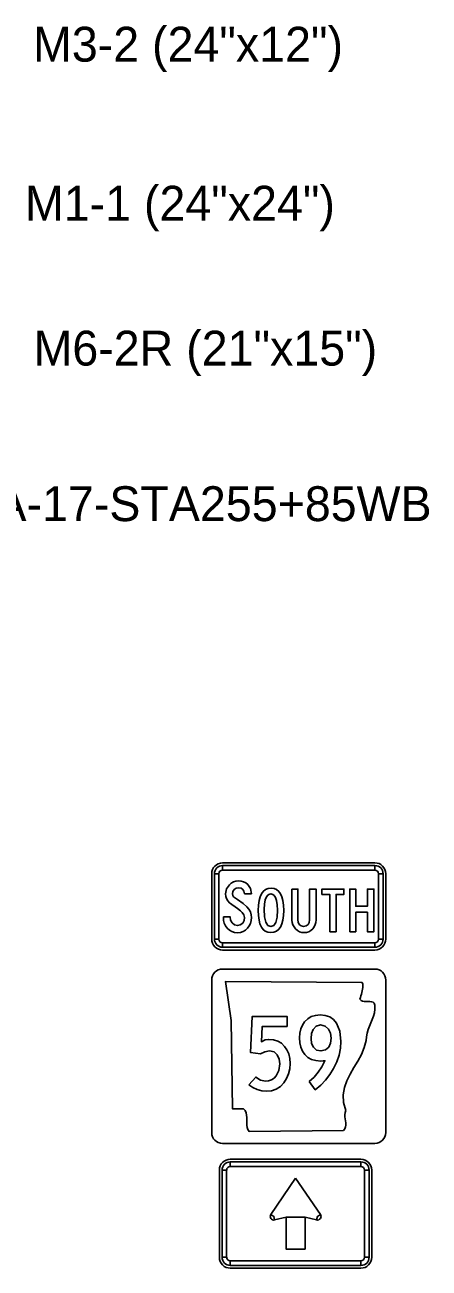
# Model space of a CAD drawing. Extents: x 620856.8 to 620948.6, y 415598.8 to 415658.2.
# Drawn here: x 620899.13 to 620903.77, y 415641.2 to 415655.46 of the extents above; entities that cross this region are included whole.
import ezdxf

# ---------------------------------------------------------------- set-up
doc = ezdxf.new("R2010")
doc.units = 0
doc.layers.add('SIGNS', color=7, linetype='Continuous')

msp = doc.modelspace()

# ---------------------------------------------------------------- linework, layer by layer
at = {"layer": 'SIGNS'}
for p, q in [((620903.15, 415645.852), (620901.4, 415645.852)), ((620901.4, 415645.769), (620901.4, 415645.821)), ((620903.15, 415645.821), (620903.15, 415645.769)), ((620901.275, 415645.727), (620901.275, 415644.977)), ((620901.306, 415645.727), (620901.358, 415645.727)), ((620903.192, 415645.727), (620903.244, 415645.727)), ((620903.275, 415644.977), (620903.275, 415645.727)), ((620901.358, 415644.977), (620901.306, 415644.977)), ((620901.4, 415644.884), (620901.4, 415644.936)), ((620903.15, 415644.936), (620903.15, 415644.884)), ((620903.244, 415644.977), (620903.192, 415644.977)), ((620901.4, 415644.852), (620903.15, 415644.852)), ((620903.15, 415644.633), (620901.4, 415644.633)), ((620901.275, 415644.508), (620901.275, 415642.758)), ((620903.275, 415642.758), (620903.275, 415644.508)), ((620901.275, 415642.758), (620901.275, 415642.758)), ((620901.4, 415642.633), (620903.15, 415642.633)), ((620902.989, 415642.453), (620901.489, 415642.453)), ((620901.489, 415642.37), (620901.489, 415642.422)), ((620902.989, 415642.422), (620902.989, 415642.37)), ((620901.364, 415642.328), (620901.364, 415641.328)), ((620901.395, 415642.328), (620901.447, 415642.328)), ((620903.031, 415642.328), (620903.083, 415642.328)), ((620903.114, 415641.328), (620903.114, 415642.328)), ((620901.989, 415641.797), (620901.954, 415641.819)), ((620901.998, 415641.757), (620901.989, 415641.797)), ((620902.489, 415641.797), (620902.48, 415641.757)), ((620902.524, 415641.819), (620902.489, 415641.797)), ((620901.447, 415641.328), (620901.395, 415641.328)), ((620901.489, 415641.235), (620901.489, 415641.287)), ((620901.489, 415641.203), (620902.989, 415641.203)), ((620902.989, 415641.287), (620902.989, 415641.235)), ((620903.083, 415641.328), (620903.031, 415641.328))]:
    msp.add_line(p, q, dxfattribs=at)
for points in [[(620903.15, 415645.821), (620901.4, 415645.821), (620901.4, 415645.769), (620903.15, 415645.769), (620903.15, 415645.821), (620903.15, 415645.821)], [(620901.306, 415645.727), (620901.306, 415644.977), (620901.358, 415644.977), (620901.358, 415645.727), (620901.306, 415645.727), (620901.306, 415645.727)], [(620901.409, 415645.232), (620901.409, 415645.227), (620901.411, 415645.192), (620901.419, 415645.16), (620901.434, 415645.131), (620901.453, 415645.104), (620901.478, 415645.08), (620901.506, 415645.063), (620901.537, 415645.053), (620901.571, 415645.049), (620901.605, 415645.053), (620901.636, 415645.063), (620901.663, 415645.079), (620901.688, 415645.102), (620901.707, 415645.128), (620901.721, 415645.158), (620901.729, 415645.189), (620901.732, 415645.224), (620901.728, 415645.257), (620901.719, 415645.289), (620901.703, 415645.319), (620901.68, 415645.347), (620901.637, 415645.384), (620901.571, 415645.43), (620901.527, 415645.462), (620901.517, 415645.479), (620901.514, 415645.498), (620901.519, 415645.524), (620901.535, 415645.545), (620901.557, 415645.56), (620901.584, 415645.565), (620901.612, 415645.56), (620901.633, 415645.546), (620901.644, 415645.527), (620901.652, 415645.498), (620901.732, 415645.498), (620901.719, 415645.557), (620901.689, 415645.603), (620901.666, 415645.621), (620901.641, 415645.634), (620901.613, 415645.641), (620901.581, 415645.644), (620901.552, 415645.641), (620901.525, 415645.633), (620901.5, 415645.619), (620901.478, 415645.6), (620901.445, 415645.552), (620901.435, 415645.496), (620901.437, 415645.467), (620901.446, 415645.441), (620901.459, 415645.417), (620901.479, 415645.394), (620901.571, 415645.328), (620901.606, 415645.302), (620901.627, 415645.282), (620901.646, 415645.254), (620901.653, 415645.223), (620901.647, 415645.189), (620901.631, 415645.161), (620901.604, 415645.14), (620901.571, 415645.133), (620901.536, 415645.14), (620901.509, 415645.164), (620901.493, 415645.195), (620901.488, 415645.232)], [(620903.244, 415644.977), (620903.244, 415645.727), (620903.192, 415645.727), (620903.192, 415644.977), (620903.244, 415644.977), (620903.244, 415644.977)], [(620902.197, 415645.551), (620902.197, 415645.196), (620902.2, 415645.167), (620902.208, 415645.14), (620902.221, 415645.116), (620902.239, 415645.094), (620902.259, 415645.075), (620902.283, 415645.062), (620902.309, 415645.054), (620902.338, 415645.051), (620902.366, 415645.054), (620902.391, 415645.062), (620902.415, 415645.076), (620902.436, 415645.096), (620902.453, 415645.118), (620902.465, 415645.143), (620902.472, 415645.169), (620902.474, 415645.197), (620902.474, 415645.551), (620902.399, 415645.551), (620902.399, 415645.2), (620902.395, 415645.169), (620902.382, 415645.145), (620902.36, 415645.128), (620902.331, 415645.122), (620902.303, 415645.128), (620902.281, 415645.146), (620902.269, 415645.171), (620902.265, 415645.2), (620902.265, 415645.551)], [(620902.632, 415645.061), (620902.703, 415645.061), (620902.703, 415645.489), (620902.794, 415645.489), (620902.794, 415645.551), (620902.542, 415645.551), (620902.542, 415645.489), (620902.632, 415645.489)], [(620902.861, 415645.061), (620902.929, 415645.061), (620902.929, 415645.286), (620903.063, 415645.286), (620903.063, 415645.061), (620903.138, 415645.061), (620903.138, 415645.551), (620903.063, 415645.551), (620903.063, 415645.354), (620902.929, 415645.354), (620902.929, 415645.551), (620902.861, 415645.551)], [(620901.4, 415644.884), (620903.15, 415644.884), (620903.15, 415644.936), (620901.4, 415644.936), (620901.4, 415644.884), (620901.4, 415644.884)], [(620903.005, 415644.479), (620903.01, 415644.46), (620903.011, 415644.44), (620903.011, 415644.421), (620903.008, 415644.402), (620903.004, 415644.383), (620903, 415644.364), (620902.994, 415644.345), (620902.988, 415644.327), (620902.983, 415644.309), (620902.978, 415644.29), (620902.992, 415644.274), (620903.009, 415644.265), (620903.029, 415644.261), (620903.051, 415644.26), (620903.072, 415644.261), (620903.093, 415644.262), (620903.112, 415644.259), (620903.128, 415644.253), (620903.141, 415644.241), (620903.149, 415644.221), (620903.15, 415644.175), (620903.144, 415644.133), (620903.134, 415644.092), (620903.119, 415644.054), (620903.104, 415644.016), (620903.088, 415643.978), (620903.073, 415643.939), (620903.061, 415643.9), (620903.052, 415643.858), (620903.05, 415643.814), (620903.028, 415643.732), (620902.994, 415643.654), (620902.954, 415643.578), (620902.909, 415643.503), (620902.866, 415643.429), (620902.829, 415643.353), (620902.801, 415643.274), (620902.786, 415643.191), (620902.789, 415643.104), (620902.815, 415643.01), (620902.808, 415642.987), (620902.805, 415642.963), (620902.806, 415642.94), (620902.809, 415642.915), (620902.812, 415642.891), (620902.815, 415642.868), (620902.815, 415642.845), (620902.812, 415642.823), (620902.804, 415642.802), (620902.788, 415642.782), (620901.704, 415642.772), (620901.69, 415642.792), (620901.681, 415642.816), (620901.678, 415642.842), (620901.677, 415642.871), (620901.678, 415642.9), (620901.678, 415642.93), (620901.676, 415642.959), (620901.671, 415642.985), (620901.66, 415643.01), (620901.641, 415643.03), (620901.515, 415643.03), (620901.497, 415644.042), (620901.433, 415644.489), (620903.005, 415644.479), (620903.005, 415644.479)], [(620901.7, 415643.307), (620901.748, 415643.274), (620901.798, 415643.251), (620901.85, 415643.237), (620901.905, 415643.233), (620901.964, 415643.238), (620902.017, 415643.257), (620902.064, 415643.287), (620902.105, 415643.33), (620902.136, 415643.378), (620902.157, 415643.43), (620902.171, 415643.488), (620902.175, 415643.551), (620902.171, 415643.608), (620902.16, 415643.66), (620902.14, 415643.706), (620902.113, 415643.747), (620902.077, 415643.782), (620902.034, 415643.806), (620901.985, 415643.821), (620901.931, 415643.827), (620901.89, 415643.82), (620901.846, 415643.8), (620901.855, 415643.975), (620902.142, 415643.975), (620902.142, 415644.091), (620901.741, 415644.091), (620901.721, 415643.675), (620901.837, 415643.66), (620901.886, 415643.686), (620901.939, 415643.695), (620901.991, 415643.683), (620902.029, 415643.648), (620902.049, 415643.602), (620902.056, 415643.545), (620902.046, 415643.47), (620902.016, 415643.409), (620901.991, 415643.382), (620901.962, 415643.363), (620901.929, 415643.352), (620901.892, 415643.348), (620901.835, 415643.36), (620901.781, 415643.395)], [(620902.989, 415642.422), (620901.489, 415642.422), (620901.489, 415642.37), (620902.989, 415642.37), (620902.989, 415642.422), (620902.989, 415642.422)], [(620901.395, 415642.328), (620901.395, 415641.328), (620901.447, 415641.328), (620901.447, 415642.328), (620901.395, 415642.328), (620901.395, 415642.328)], [(620902.239, 415642.235), (620901.954, 415641.819), (620901.989, 415641.797), (620901.998, 415641.757), (620902.13, 415641.787), (620902.348, 415641.787), (620902.48, 415641.757), (620902.489, 415641.797), (620902.524, 415641.819), (620902.239, 415642.235), (620902.239, 415642.235)], [(620903.083, 415641.328), (620903.083, 415642.328), (620903.031, 415642.328), (620903.031, 415641.328), (620903.083, 415641.328), (620903.083, 415641.328)], [(620902.348, 415641.422), (620902.13, 415641.422), (620902.13, 415641.787), (620902.348, 415641.787), (620902.348, 415641.422), (620902.348, 415641.422)], [(620901.489, 415641.235), (620902.989, 415641.235), (620902.989, 415641.287), (620901.489, 415641.287), (620901.489, 415641.235), (620901.489, 415641.235)]]:
    msp.add_lwpolyline(points, close=True, dxfattribs=at)
for points in [[(620902.102, 415645.306), (620902.1, 415645.366), (620902.093, 415645.418), (620902.082, 415645.461), (620902.066, 415645.497), (620902.045, 415645.525), (620902.02, 415645.545), (620901.991, 415645.556), (620901.957, 415645.561), (620901.923, 415645.556), (620901.893, 415645.545), (620901.868, 415645.525), (620901.847, 415645.497), (620901.831, 415645.461), (620901.819, 415645.418), (620901.813, 415645.366), (620901.81, 415645.306), (620901.812, 415645.246), (620901.819, 415645.195), (620901.83, 415645.151), (620901.846, 415645.115), (620901.866, 415645.087), (620901.891, 415645.067), (620901.92, 415645.055), (620901.954, 415645.051), (620901.989, 415645.055), (620902.019, 415645.067), (620902.044, 415645.087), (620902.065, 415645.115), (620902.081, 415645.151), (620902.093, 415645.195), (620902.1, 415645.246), (620902.102, 415645.306)], [(620902.031, 415645.309), (620902.027, 415645.227), (620902.012, 415645.169), (620901.988, 415645.134), (620901.955, 415645.122), (620901.921, 415645.135), (620901.897, 415645.172), (620901.882, 415645.234), (620901.878, 415645.321), (620901.881, 415645.379), (620901.89, 415645.427), (620901.901, 415645.456), (620901.916, 415645.478), (620901.933, 415645.49), (620901.955, 415645.495), (620901.976, 415645.49), (620901.994, 415645.476), (620902.008, 415645.453), (620902.02, 415645.421), (620902.028, 415645.37), (620902.031, 415645.309)], [(620901.4, 415644.633), (620901.4, 415644.633)], [(620903.15, 415644.633), (620903.15, 415644.633)], [(620901.275, 415644.508), (620901.275, 415644.508)], [(620902.396, 415643.344), (620902.464, 415643.249), (620902.527, 415643.302), (620902.583, 415643.36), (620902.632, 415643.424), (620902.676, 415643.494), (620902.712, 415643.57), (620902.738, 415643.647), (620902.753, 415643.725), (620902.759, 415643.804), (620902.746, 415643.923), (620902.709, 415644.014), (620902.674, 415644.055), (620902.631, 415644.084), (620902.58, 415644.101), (620902.521, 415644.107), (620902.467, 415644.102), (620902.419, 415644.088), (620902.378, 415644.064), (620902.343, 415644.03), (620902.317, 415643.991), (620902.298, 415643.947), (620902.287, 415643.898), (620902.284, 415643.844), (620902.287, 415643.786), (620902.299, 415643.736), (620902.318, 415643.691), (620902.345, 415643.653), (620902.381, 415643.62), (620902.423, 415643.597), (620902.473, 415643.583), (620902.53, 415643.578), (620902.554, 415643.58), (620902.577, 415643.582), (620902.575, 415643.582), (620902.541, 415643.512), (620902.5, 415643.45), (620902.452, 415643.394), (620902.396, 415643.344)], [(620902.647, 415643.841), (620902.64, 415643.784), (620902.619, 415643.739), (620902.582, 415643.706), (620902.53, 415643.695), (620902.48, 415643.705), (620902.443, 415643.737), (620902.422, 415643.781), (620902.416, 415643.836), (620902.421, 415643.894), (620902.439, 415643.941), (620902.475, 415643.979), (620902.526, 415643.992), (620902.577, 415643.98), (620902.617, 415643.944), (620902.639, 415643.897), (620902.647, 415643.841)], [(620901.4, 415642.633), (620901.4, 415642.633)], [(620903.15, 415642.633), (620903.15, 415642.633)]]:
    msp.add_lwpolyline(points, dxfattribs=at)
for centre, radius, start, end in [((620901.4, 415645.727), 0.125, 90.0002, 179.9998), ((620901.4, 415645.727), 0.0937, 90.0002, 179.9998), ((620901.4, 415645.727), 0.0417, 90.0002, 179.9998), ((620903.15, 415645.727), 0.125, 360, 90.0002), ((620903.15, 415645.727), 0.0937, 360, 90.0002), ((620903.15, 415645.727), 0.0417, 360, 90.0002), ((620901.4, 415644.977), 0.125, 179.9998, 270.0001), ((620901.4, 415644.977), 0.0937, 179.9998, 270.0001), ((620901.4, 415644.977), 0.0417, 179.9998, 270.0001), ((620903.15, 415644.977), 0.125, 270.0001, 0.0003), ((620903.15, 415644.977), 0.0937, 270.0001, 0.0003), ((620903.15, 415644.977), 0.0417, 270.0001, 0.0003), ((620901.4, 415644.508), 0.125, 90.0002, 179.9998), ((620903.15, 415644.508), 0.125, 360, 90), ((620901.4, 415642.758), 0.125, 180, 270), ((620903.15, 415642.758), 0.125, 270.0001, 0.0003), ((620901.489, 415642.328), 0.125, 90.0002, 179.9998), ((620901.489, 415642.328), 0.0937, 90.0002, 179.9998), ((620901.489, 415642.328), 0.0417, 90.0002, 179.9998), ((620902.989, 415642.328), 0.125, 360, 90.0002), ((620902.989, 415642.328), 0.0937, 360, 90.0002), ((620902.989, 415642.328), 0.0417, 360, 90.0002), ((620901.989, 415641.797), 0.0417, 147.7246, 282.9506), ((620902.489, 415641.797), 0.0417, 257.0495, 32.2756), ((620901.489, 415641.328), 0.125, 179.9998, 270.0001), ((620901.489, 415641.328), 0.0937, 179.9998, 270.0001), ((620901.489, 415641.328), 0.0417, 179.9998, 270.0001), ((620902.989, 415641.328), 0.0937, 270.0001, 0.0003), ((620902.989, 415641.328), 0.0417, 270.0001, 0.0003), ((620902.989, 415641.328), 0.125, 270.0001, 0.0003)]:
    msp.add_arc(centre, radius, start, end, dxfattribs=at)

# ---------------------------------------------------------------- texts
for s, p in [('M3-2 (24"x12")', (620899.223, 415655.041)), ('M1-1 (24"x24")', (620899.13, 415653.217)), ('M6-2R (21"x15")', (620899.229, 415651.555)), ('SS-RAMP2A-17-STA255+85WB', (620896.057, 415649.771))]:
    msp.add_text(s, height=0.4, rotation=0, dxfattribs=at).set_placement(p)

doc.saveas('drawing.dxf')
